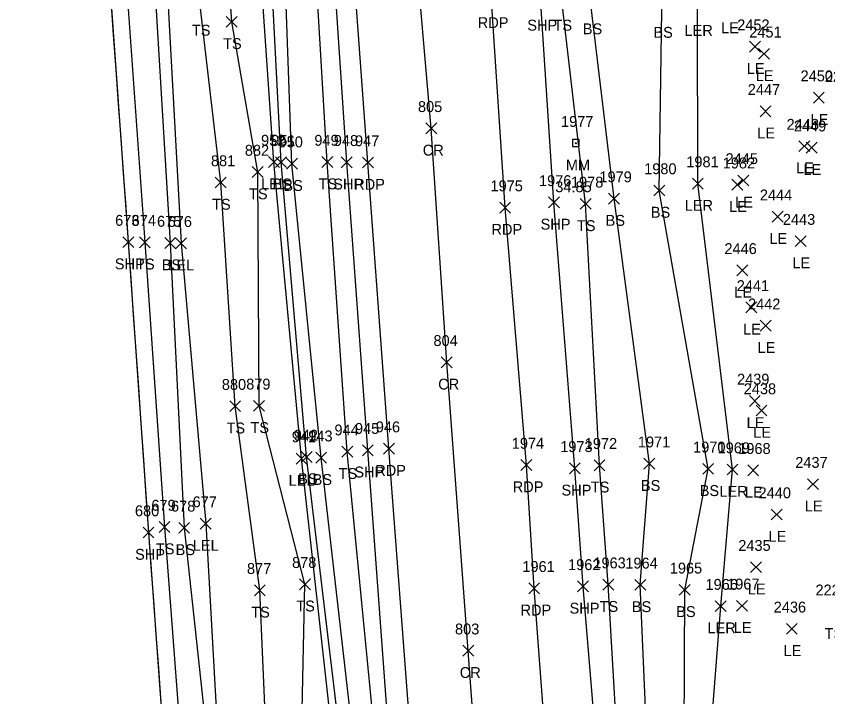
# Model space of a CAD drawing. Extents: x 1650221 to 1650634, y 244606 to 249996.
# Drawn here: x 1650345.8 to 1650494.9, y 245336 to 245461.1 of the extents above; entities that cross this region are included whole.
import ezdxf

# ---------------------------------------------------------------- set-up
doc = ezdxf.new("R2010")
doc.units = 0
for name, color, linetype in [('L_A', 7, 'Continuous'), ('L_I', 7, 'Continuous'), ('L_TIC', 7, 'Continuous'), ('LARO', 7, 'Continuous'), ('LELB', 7, 'Continuous'), ('LSOGP', 7, 'Continuous'), ('P_A', 7, 'Continuous'), ('P_I', 7, 'Continuous'), ('P_TIC', 7, 'Continuous'), ('PET', 7, 'Continuous'), ('PRC', 7, 'Continuous'), ('PSP', 7, 'Continuous'), ('S_A', 7, 'Continuous'), ('S_C', 7, 'Continuous'), ('S_I', 7, 'Continuous'), ('SRM', 7, 'Continuous')]:
    doc.layers.add(name, color=color, linetype=linetype)

msp = doc.modelspace()

# ---------------------------------------------------------------- linework, layer by layer
at = {"layer": 'L_TIC'}
for points in [[(1650384.39, 245459.04), (1650386.39, 245461.04)], [(1650386.39, 245459.04), (1650384.39, 245461.04)], [(1650480.56, 245454.48), (1650482.56, 245456.48)], [(1650482.56, 245454.48), (1650480.56, 245456.48)], [(1650482.21, 245453.16), (1650484.21, 245455.16)], [(1650484.21, 245453.16), (1650482.21, 245455.16)], [(1650492.3, 245445.11), (1650494.3, 245447.11)], [(1650494.3, 245445.11), (1650492.3, 245447.11)], [(1650482.5, 245442.61), (1650484.5, 245444.61)], [(1650484.5, 245442.61), (1650482.5, 245444.61)], [(1650489.64, 245436.2), (1650491.64, 245438.2)], [(1650491.64, 245436.2), (1650489.64, 245438.2)], [(1650490.98, 245435.9), (1650492.98, 245437.9)], [(1650492.98, 245435.9), (1650490.98, 245437.9)], [(1650392.14, 245433.28), (1650394.14, 245435.28)], [(1650394.14, 245433.28), (1650392.14, 245435.28)], [(1650393.45, 245433.24), (1650395.45, 245435.24)], [(1650395.45, 245433.24), (1650393.45, 245435.24)], [(1650395.45, 245432.97), (1650397.45, 245434.97)], [(1650397.45, 245432.97), (1650395.45, 245434.97)], [(1650401.95, 245433.27), (1650403.95, 245435.27)], [(1650403.95, 245433.27), (1650401.95, 245435.27)], [(1650389.16, 245431.43), (1650391.16, 245433.43)], [(1650391.16, 245431.43), (1650389.16, 245433.43)], [(1650478.42, 245429.89), (1650480.42, 245431.89)], [(1650480.42, 245429.89), (1650478.42, 245431.89)], [(1650382.37, 245429.51), (1650384.37, 245431.51)], [(1650384.37, 245429.51), (1650382.37, 245431.51)], [(1650470.06, 245429.31), (1650472.06, 245431.31)], [(1650472.06, 245429.31), (1650470.06, 245431.31)], [(1650477.33, 245429.1), (1650479.33, 245431.1)], [(1650479.33, 245429.1), (1650477.33, 245431.1)], [(1650462.98, 245428.04), (1650464.98, 245430.04)], [(1650464.98, 245428.04), (1650462.98, 245430.04)], [(1650449.43, 245425.58), (1650451.43, 245427.58)], [(1650451.43, 245425.58), (1650449.43, 245427.58)], [(1650454.67, 245426.55), (1650456.67, 245428.55)], [(1650456.67, 245426.55), (1650454.67, 245428.55)], [(1650484.72, 245423.22), (1650486.72, 245425.22)], [(1650486.72, 245423.22), (1650484.72, 245425.22)], [(1650368.41, 245418.53), (1650370.41, 245420.53)], [(1650370.41, 245418.53), (1650368.41, 245420.53)], [(1650373.07, 245418.38), (1650375.07, 245420.38)], [(1650375.07, 245418.38), (1650373.07, 245420.38)], [(1650375.08, 245418.34), (1650377.08, 245420.34)], [(1650377.08, 245418.34), (1650375.08, 245420.34)], [(1650488.95, 245418.73), (1650490.95, 245420.73)], [(1650490.95, 245418.73), (1650488.95, 245420.73)], [(1650478.26, 245413.36), (1650480.26, 245415.36)], [(1650480.26, 245413.36), (1650478.26, 245415.36)], [(1650479.9, 245406.55), (1650481.9, 245408.55)], [(1650481.9, 245406.55), (1650479.9, 245408.55)], [(1650482.55, 245403.18), (1650484.55, 245405.18)], [(1650484.55, 245403.18), (1650482.55, 245405.18)], [(1650385.02, 245388.39), (1650387.02, 245390.39)], [(1650387.02, 245388.39), (1650385.02, 245390.39)], [(1650389.42, 245388.46), (1650391.42, 245390.46)], [(1650391.42, 245388.46), (1650389.42, 245390.46)], [(1650480.54, 245389.36), (1650482.54, 245391.36)], [(1650482.54, 245389.36), (1650480.54, 245391.36)], [(1650481.76, 245387.6), (1650483.76, 245389.6)], [(1650483.76, 245387.6), (1650481.76, 245389.6)], [(1650398.15, 245379.06), (1650400.15, 245381.06)], [(1650400.15, 245379.06), (1650398.15, 245381.06)], [(1650405.63, 245380.03), (1650407.63, 245382.03)], [(1650407.63, 245380.03), (1650405.63, 245382.03)], [(1650397.22, 245378.76), (1650399.22, 245380.76)], [(1650399.22, 245378.76), (1650397.22, 245380.76)], [(1650400.82, 245378.92), (1650402.82, 245380.92)], [(1650402.82, 245378.92), (1650400.82, 245380.92)], [(1650461.16, 245377.82), (1650463.16, 245379.82)], [(1650463.16, 245377.82), (1650461.16, 245379.82)], [(1650451.98, 245377.54), (1650453.98, 245379.54)], [(1650453.98, 245377.54), (1650451.98, 245379.54)], [(1650471.97, 245376.88), (1650473.97, 245378.88)], [(1650473.97, 245376.88), (1650471.97, 245378.88)], [(1650476.44, 245376.75), (1650478.44, 245378.75)], [(1650478.44, 245376.75), (1650476.44, 245378.75)], [(1650480.23, 245376.61), (1650482.23, 245378.61)], [(1650482.23, 245376.61), (1650480.23, 245378.61)], [(1650491.23, 245374.06), (1650493.23, 245376.06)], [(1650493.23, 245374.06), (1650491.23, 245376.06)], [(1650484.57, 245368.48), (1650486.57, 245370.48)], [(1650486.57, 245368.48), (1650484.57, 245370.48)], [(1650372.04, 245366.18), (1650374.04, 245368.18)], [(1650374.04, 245366.18), (1650372.04, 245368.18)], [(1650375.64, 245366.03), (1650377.64, 245368.03)], [(1650377.64, 245366.03), (1650375.64, 245368.03)], [(1650379.61, 245366.82), (1650381.61, 245368.82)], [(1650381.61, 245366.82), (1650379.61, 245368.82)], [(1650480.76, 245358.8), (1650482.76, 245360.8)], [(1650482.76, 245358.8), (1650480.76, 245360.8)], [(1650397.84, 245355.67), (1650399.84, 245357.67)], [(1650399.84, 245355.67), (1650397.84, 245357.67)], [(1650453.6, 245355.59), (1650455.6, 245357.59)], [(1650455.6, 245355.59), (1650453.6, 245357.59)], [(1650459.48, 245355.55), (1650461.48, 245357.55)], [(1650461.48, 245355.55), (1650459.48, 245357.55)], [(1650389.56, 245354.55), (1650391.56, 245356.55)], [(1650391.56, 245354.55), (1650389.56, 245356.55)], [(1650467.65, 245354.64), (1650469.65, 245356.64)], [(1650469.65, 245354.64), (1650467.65, 245356.64)], [(1650474.26, 245351.64), (1650476.26, 245353.64)], [(1650476.26, 245351.64), (1650474.26, 245353.64)], [(1650478.19, 245351.7), (1650480.19, 245353.7)], [(1650480.19, 245351.7), (1650478.19, 245353.7)], [(1650487.33, 245347.47), (1650489.33, 245349.47)], [(1650489.33, 245347.47), (1650487.33, 245349.47)]]:
    msp.add_lwpolyline(points, dxfattribs=at)
at = {"layer": 'LARO'}
for points in [[(1650491, 245121.86), (1650493.61, 245139.73), (1650488.81, 245187.64), (1650492.44, 245198.75), (1650485.3, 245221.37), (1650479.96, 245259.68), (1650476.93, 245285.6), (1650472.44, 245315.86), (1650475.26, 245352.64), (1650477.44, 245377.75), (1650471.06, 245430.31), (1650471.03, 245462.47), (1650469.65, 245517.3), (1650470.03, 245548.03), (1650459.64, 245596.52), (1650458.35, 245631.93), (1650449.5, 245684.33)], [(1650421.38, 244936.36), (1650423.35, 244936.27), (1650425.89, 244936.22), (1650434.3, 244938.37), (1650430.48, 244972), (1650427.02, 245018.52), (1650423.68, 245067.08), (1650420.77, 245123.48), (1650416.16, 245170.75), (1650416.29, 245170.75), (1650411.97, 245219.01), (1650407.36, 245272.17), (1650403.92, 245328.57), (1650398.22, 245379.76), (1650393.14, 245434.28), (1650390.04, 245478.89), (1650387.05, 245523.12), (1650386.02, 245551.2)], [(1650370.23, 245505.43), (1650373.27, 245470.75), (1650376.08, 245419.34), (1650380.61, 245367.82), (1650383.54, 245316.3), (1650388.29, 245270.51), (1650390.54, 245221.61), (1650394.38, 245168.62), (1650397.75, 245118.3), (1650404.08, 245063.51), (1650406.12, 245018.23), (1650409.93, 244966.8), (1650411.89, 244938.28)]]:
    msp.add_lwpolyline(points, dxfattribs=at)
at = {"layer": 'LELB'}
for points in [[(1650349.13, 245703.09), (1650351.39, 245660.59), (1650355.99, 245608.05), (1650358.47, 245560.96), (1650362.91, 245508.7), (1650365.76, 245471.06), (1650369.41, 245419.53), (1650373.04, 245367.18), (1650376.89, 245316.29), (1650379.01, 245269.77), (1650383.48, 245220.96), (1650387.1, 245168.26), (1650390.97, 245118.17), (1650394.99, 245063.19), (1650398.03, 245017.1), (1650401.94, 244967.25), (1650403.81, 244936.86), (1650407.34, 244889.23), (1650410.84, 244834.73), (1650414.52, 244785.95), (1650419.34, 244732.83), (1650422.93, 244682.99), (1650426.36, 244632.18), (1650427.51, 244611.7)], [(1650355.71, 245703.22), (1650358.45, 245660.47), (1650361.92, 245609.02), (1650362.95, 245561.76), (1650366.97, 245508.68), (1650370.97, 245471.38), (1650374.07, 245419.38), (1650376.64, 245367.03), (1650382.18, 245316.08), (1650385.68, 245270.43), (1650388.77, 245221.07), (1650390.77, 245168.69), (1650394.69, 245118), (1650401.29, 245063.19), (1650403.89, 245017.69), (1650406.99, 244966.96), (1650408.31, 244937.61), (1650413.12, 244889.16), (1650416.09, 244835.73), (1650420.51, 244786.1), (1650423.8, 244733.3), (1650426.51, 244682.57), (1650434.12, 244632.73), (1650437.01, 244612.78)], [(1650458.26, 244631.23), (1650456.79, 244671.65), (1650452.78, 244720.4), (1650448.37, 244766.08), (1650444.9, 244801.26), (1650441.62, 244837.94), (1650439.87, 244879.23), (1650437.68, 244923.9), (1650433.87, 244972.21), (1650429.49, 245017.89), (1650426.15, 245066.7), (1650422.69, 245123.12), (1650419.86, 245170.84), (1650416.52, 245219.13), (1650411.95, 245271.56), (1650407.71, 245328.35), (1650401.82, 245379.92), (1650396.45, 245433.97), (1650394.84, 245478.56), (1650392.49, 245522.5), (1650389.35, 245551.29), (1650385.12, 245588.75), (1650380.77, 245632.36), (1650373.15, 245685.41)], [(1650462.3, 244631.92), (1650459.1, 244671.43), (1650455.6, 244720.68), (1650451.8, 244765.92), (1650449.21, 244801.88), (1650446.61, 244838.72), (1650443.38, 244880.99), (1650440.04, 244922.8), (1650437.91, 244972.67), (1650433.82, 245018.12), (1650431.01, 245067.65), (1650425.84, 245123.86), (1650424.05, 245171.63), (1650419.6, 245218.92), (1650416.04, 245272.16), (1650411.76, 245328.09), (1650406.63, 245381.03), (1650402.95, 245434.27), (1650400.25, 245479.81), (1650396.41, 245522.79), (1650395.43, 245551.92), (1650392.44, 245589.61), (1650388.27, 245633.5), (1650384.04, 245685.26)], [(1650489.71, 244991.22), (1650489.69, 245009.71), (1650486.09, 245047.64), (1650483.87, 245079.25), (1650480.92, 245116.18), (1650479.42, 245140.42), (1650476.29, 245187.3), (1650474, 245221.05), (1650469.02, 245258.31), (1650465.71, 245285.05), (1650462.26, 245315.54), (1650460.48, 245356.55), (1650462.16, 245378.82), (1650455.67, 245427.55), (1650451.48, 245462.76), (1650449.79, 245512.44), (1650449.11, 245548.12), (1650443.42, 245590.47), (1650442.32, 245632.05), (1650435.43, 245684.43)], [(1650471.05, 245115.28), (1650468.74, 245140.33), (1650464.89, 245185.98), (1650463.25, 245221.34), (1650461.37, 245257.85), (1650459.32, 245284.8), (1650456.97, 245315.55), (1650454.6, 245356.59), (1650452.98, 245378.54), (1650450.43, 245426.58), (1650446.12, 245463.42), (1650443.52, 245512.09), (1650441.71, 245548.12), (1650438.37, 245589.38), (1650434.29, 245631.65), (1650429.68, 245683.37)], [(1650493.15, 245007.74), (1650488.13, 245047.67), (1650486.59, 245079.09), (1650485.35, 245117.44), (1650483.97, 245140), (1650485.34, 245188.31), (1650482.43, 245221.37), (1650477.25, 245258), (1650473.1, 245285.62), (1650468.47, 245315.46), (1650468.65, 245355.64), (1650472.97, 245377.88), (1650463.98, 245429.04), (1650464.45, 245462.11), (1650460.79, 245514.67), (1650465.46, 245547.92), (1650447.43, 245596.3), (1650450.46, 245632.25)], [(1650417.42, 245170.71), (1650414.29, 245218.92), (1650409.59, 245271.3), (1650405.4, 245327.96), (1650399.15, 245380.06), (1650394.45, 245434.24), (1650392.17, 245479.25), (1650388.55, 245523.47), (1650387.04, 245550.93), (1650374.54, 245599.04)], [(1650411.56, 245100.31), (1650410.98, 245134.62), (1650407.62, 245167.58), (1650401.15, 245195.95), (1650400.96, 245232.6), (1650396.91, 245255.72), (1650396.39, 245280.59), (1650392.18, 245317.33), (1650390.56, 245355.55), (1650386.02, 245389.39), (1650383.37, 245430.51), (1650379.67, 245462.51), (1650379.96, 245467.43), (1650380, 245489.06), (1650377.56, 245510.96), (1650374.72, 245546.33), (1650373.24, 245560.96), (1650373.27, 245589.26)], [(1650417.99, 245100.65), (1650416.66, 245133.49), (1650414.16, 245167.69), (1650410.2, 245197), (1650406.67, 245233.63), (1650402.8, 245260.5), (1650403.69, 245281.19), (1650397.99, 245316.2), (1650398.84, 245356.67), (1650390.42, 245389.46), (1650390.16, 245432.43), (1650385.39, 245460.04), (1650384.98, 245466.18), (1650387.77, 245488.08), (1650384.3, 245517.36), (1650381.95, 245546.8), (1650375.57, 245561.13), (1650373.27, 245589.26)]]:
    msp.add_lwpolyline(points, dxfattribs=at)
at = {"layer": 'LSOGP'}
msp.add_lwpolyline([(1650363.17, 245464), (1650363.62, 245457.65), (1650364.08, 245451.3), (1650364.54, 245444.95), (1650365, 245438.6), (1650365.45, 245432.25), (1650365.91, 245425.9), (1650366.37, 245419.55), (1650366.83, 245412.88), (1650367.3, 245406.21), (1650367.76, 245399.53), (1650368.23, 245392.86), (1650368.7, 245386.19), (1650369.16, 245379.52), (1650369.63, 245372.84), (1650370.09, 245366.17), (1650370.55, 245359.92), (1650371, 245353.67), (1650371.46, 245347.41), (1650371.91, 245341.16), (1650372.37, 245334.91)], dxfattribs=at)
at = {"layer": 'P_TIC'}
for points in [[(1650421.06, 245439.46), (1650423.06, 245441.46)], [(1650423.06, 245439.46), (1650421.06, 245441.46)], [(1650405.52, 245433.23), (1650407.52, 245435.23)], [(1650407.52, 245433.23), (1650405.52, 245435.23)], [(1650409.42, 245433.18), (1650411.42, 245435.18)], [(1650411.42, 245433.18), (1650409.42, 245435.18)], [(1650443.62, 245425.85), (1650445.62, 245427.85)], [(1650445.62, 245425.85), (1650443.62, 245427.85)], [(1650434.64, 245424.9), (1650436.64, 245426.9)], [(1650436.64, 245424.9), (1650434.64, 245426.9)], [(1650365.37, 245418.55), (1650367.37, 245420.55)], [(1650367.37, 245418.55), (1650365.37, 245420.55)], [(1650423.91, 245396.45), (1650425.91, 245398.45)], [(1650425.91, 245396.45), (1650423.91, 245398.45)], [(1650413.28, 245380.59), (1650415.28, 245382.59)], [(1650415.28, 245380.59), (1650413.28, 245382.59)], [(1650409.4, 245380.3), (1650411.4, 245382.3)], [(1650411.4, 245380.3), (1650409.4, 245382.3)], [(1650438.55, 245377.58), (1650440.55, 245379.58)], [(1650440.55, 245377.58), (1650438.55, 245379.58)], [(1650447.46, 245376.97), (1650449.46, 245378.97)], [(1650449.46, 245376.97), (1650447.46, 245378.97)], [(1650369.09, 245365.17), (1650371.09, 245367.17)], [(1650371.09, 245365.17), (1650369.09, 245367.17)], [(1650448.96, 245355.27), (1650450.96, 245357.27)], [(1650450.96, 245355.27), (1650448.96, 245357.27)], [(1650439.98, 245354.92), (1650441.98, 245356.92)], [(1650441.98, 245354.92), (1650439.98, 245356.92)], [(1650427.87, 245343.44), (1650429.87, 245345.44)], [(1650429.87, 245343.44), (1650427.87, 245345.44)]]:
    msp.add_lwpolyline(points, dxfattribs=at)
at = {"layer": 'PET'}
for points in [[(1650468.61, 244633.66), (1650465.16, 244679.18), (1650461.18, 244730.39), (1650457.78, 244777.29), (1650455.76, 244806.01), (1650453.3, 244838.79), (1650450.33, 244880.04), (1650447.22, 244922.32), (1650443.48, 244972.73), (1650440.49, 245018.18), (1650436.73, 245069.12), (1650432.63, 245123.79), (1650429.44, 245172.68), (1650426.2, 245218.76), (1650422.12, 245272.82), (1650418.28, 245328.28), (1650414.28, 245381.59), (1650410.42, 245434.18), (1650407.03, 245480.26), (1650404.25, 245522.13), (1650401.81, 245552.98), (1650399.16, 245589.27), (1650395.97, 245634.45), (1650392.36, 245685.55)], [(1650458.15, 245114.32), (1650456.62, 245139.84), (1650453.42, 245185.54), (1650451.1, 245220.97), (1650448.32, 245256.66), (1650446.89, 245283.96), (1650444.13, 245314.19), (1650440.98, 245355.92), (1650439.55, 245378.58), (1650435.64, 245425.9), (1650433.13, 245463.89), (1650429.51, 245512.19), (1650427.14, 245547.69), (1650424.3, 245587.11), (1650421.18, 245630.65), (1650417.91, 245681.78)]]:
    msp.add_lwpolyline(points, dxfattribs=at)
at = {"layer": 'PRC'}
msp.add_lwpolyline([(1650447.57, 245085.81), (1650443.28, 245144.22), (1650439.84, 245189.25), (1650436.21, 245244.62), (1650432.57, 245294.06), (1650428.87, 245344.44), (1650424.91, 245397.45), (1650422.06, 245440.46), (1650418.2, 245485.2), (1650414.81, 245534.63), (1650412.73, 245565.5), (1650409.49, 245611.37), (1650407.05, 245649.82), (1650403.01, 245697.04)], dxfattribs=at)
at = {"layer": 'PSP'}
for points in [[(1650345.78, 245703.18), (1650348.63, 245659.65), (1650352.24, 245608.27), (1650356.14, 245560.76), (1650359.83, 245508.67), (1650362.71, 245470.35), (1650366.37, 245419.55), (1650370.09, 245366.17), (1650373.73, 245316.16), (1650376.75, 245269.64), (1650380.21, 245220.67), (1650384.07, 245168.16), (1650387.54, 245117.86), (1650391.85, 245063.26), (1650394.9, 245017.42), (1650398.56, 244967.17), (1650400.8, 244936.49), (1650404.42, 244889.02), (1650408.47, 244833.97), (1650411.77, 244786.13), (1650415.79, 244732.16), (1650419.27, 244682.87), (1650423.02, 244632.43), (1650424.78, 244611.26)], [(1650464.84, 244632.07), (1650461.81, 244671.31), (1650457.94, 244720.75), (1650454.77, 244765.54), (1650451.99, 244802.46), (1650449.34, 244838.71), (1650446.5, 244879.72), (1650443.46, 244922.98), (1650439.98, 244973.19), (1650436.37, 245018.02), (1650433.26, 245068.28), (1650429.09, 245123.84), (1650425.59, 245171.99), (1650422.33, 245218.99), (1650418.38, 245272.19), (1650414.3, 245328), (1650410.4, 245381.3), (1650406.52, 245434.23), (1650403.48, 245480), (1650400.24, 245522.79), (1650398.25, 245552.46), (1650395.41, 245589.43), (1650392.23, 245633.8), (1650388.44, 245685.1)], [(1650467.35, 245115.19), (1650465.66, 245140.38), (1650462.4, 245185.76), (1650459.93, 245221.23), (1650457.1, 245257.2), (1650455.22, 245284.62), (1650453.41, 245314.94), (1650449.96, 245356.27), (1650448.46, 245377.97), (1650444.62, 245426.85), (1650442.19, 245463.43), (1650438.55, 245512.23), (1650436.23, 245548.05), (1650433.37, 245588.35), (1650430.25, 245631.19), (1650426.21, 245683.01)]]:
    msp.add_lwpolyline(points, dxfattribs=at)
at = {"layer": 'SRM'}
for p, q in [((1650449.26, 245438.39), (1650448.01, 245438.39)), ((1650448.01, 245438.39), (1650448.01, 245437.14)), ((1650449.26, 245438.39), (1650448.01, 245438.39)), ((1650448.01, 245438.39), (1650448.01, 245437.14)), ((1650449.26, 245437.14), (1650449.26, 245438.39)), ((1650449.26, 245437.14), (1650449.26, 245438.39)), ((1650448.01, 245437.14), (1650449.26, 245437.14)), ((1650448.01, 245437.14), (1650449.26, 245437.14))]:
    msp.add_line(p, q, dxfattribs=at)
msp.add_circle((1650448.61, 245437.73), 0.0833, dxfattribs=at)

# ---------------------------------------------------------------- texts
at = {"layer": 'L_A'}
for s, p in [('TS', (1650444.53, 245458.42)), ('TS', (1650378.07, 245457.51)), ('BS', (1650449.92, 245457.76)), ('BS', (1650462.9, 245457.11)), ('LER', (1650468.61, 245457.47)), ('LE', (1650475.35, 245457.96)), ('TS', (1650383.8, 245455.04)), ('LE', (1650480.05, 245450.48)), ('LE', (1650481.7, 245449.16)), ('LE', (1650491.79, 245441.11)), ('LE', (1650481.98, 245438.61)), ('LE', (1650489.12, 245432.2)), ('LE', (1650490.47, 245431.9)), ('LEL', (1650390.78, 245429.28)), ('BS', (1650392.89, 245429.24)), ('BS', (1650394.89, 245428.97)), ('TS', (1650401.36, 245429.27)), ('TS', (1650388.57, 245427.43)), ('TS', (1650381.78, 245425.51)), ('LER', (1650468.65, 245425.31)), ('LE', (1650477.91, 245425.89)), ('BS', (1650462.42, 245424.04)), ('LE', (1650476.82, 245425.1)), ('BS', (1650454.11, 245422.55)), ('TS', (1650448.84, 245421.58)), ('LE', (1650484.2, 245419.22)), ('TS', (1650367.81, 245414.53)), ('BS', (1650372.51, 245414.38)), ('LEL', (1650373.72, 245414.34)), ('LE', (1650488.44, 245414.73)), ('LE', (1650477.75, 245409.36)), ('LE', (1650479.39, 245402.55)), ('LE', (1650482.04, 245399.18)), ('LE', (1650480.03, 245385.36)), ('TS', (1650384.43, 245384.39)), ('TS', (1650388.83, 245384.46)), ('LE', (1650481.25, 245383.6)), ('LEL', (1650395.85, 245374.76)), ('BS', (1650397.6, 245375.06)), ('BS', (1650400.26, 245374.92)), ('TS', (1650405.04, 245376.03)), ('TS', (1650451.39, 245373.54)), ('BS', (1650460.6, 245373.82)), ('BS', (1650471.41, 245372.88)), ('LER', (1650475.02, 245372.75)), ('LE', (1650479.72, 245372.61)), ('LE', (1650490.72, 245370.06)), ('LE', (1650484.06, 245364.48)), ('LEL', (1650378.24, 245362.82)), ('TS', (1650371.45, 245362.18)), ('BS', (1650375.08, 245362.03)), ('LE', (1650480.24, 245354.8)), ('TS', (1650397.25, 245351.67)), ('TS', (1650453.01, 245351.59)), ('BS', (1650458.93, 245351.55)), ('TS', (1650388.97, 245350.55)), ('BS', (1650467.09, 245350.64)), ('LER', (1650472.84, 245347.64)), ('LE', (1650477.67, 245347.7)), ('TS', (1650494.36, 245346.61)), ('LE', (1650486.82, 245343.47))]:
    msp.add_text(s, height=2, dxfattribs=at).set_placement(p)
at = {"layer": 'L_I'}
for s, p in [('2452', (1650478.3, 245458.48)), ('2451', (1650480.52, 245457.16)), ('2450', (1650489.95, 245449.11)), ('2229', (1650494.41, 245448.99)), ('2447', (1650480.24, 245446.61)), ('2448', (1650487.38, 245440.2)), ('2449', (1650488.71, 245439.9)), ('952', (1650390.78, 245437.28)), ('951', (1650392.65, 245437.24)), ('949', (1650400.58, 245437.27)), ('950', (1650394, 245436.97)), ('882', (1650387.8, 245435.43)), ('881', (1650381.57, 245433.51)), ('1981', (1650468.94, 245433.31)), ('1982', (1650475.64, 245433.1)), ('2445', (1650476.16, 245433.89)), ('1980', (1650461.2, 245432.04)), ('1979', (1650452.97, 245430.55)), ('1978', (1650447.74, 245429.58)), ('2444', (1650482.46, 245427.22)), ('674', (1650367, 245422.53)), ('675', (1650371.66, 245422.38)), ('676', (1650373.62, 245422.34)), ('2443', (1650486.69, 245422.73)), ('2446', (1650475.95, 245417.36)), ('2441', (1650478.21, 245410.55)), ('2442', (1650480.29, 245407.18)), ('879', (1650388.05, 245392.46)), ('2439', (1650478.27, 245393.36)), ('880', (1650383.57, 245392.39)), ('2438', (1650479.5, 245391.6)), ('944', (1650404.27, 245384.03)), ('941', (1650396.42, 245382.76)), ('942', (1650396.79, 245383.06)), ('943', (1650399.46, 245382.92)), ('1972', (1650450.28, 245381.54)), ('1971', (1650460.04, 245381.82)), ('1970', (1650470.19, 245380.88)), ('1969', (1650474.69, 245380.75)), ('1968', (1650478.49, 245380.61)), ('2437', (1650488.97, 245378.06)), ('2440', (1650482.23, 245372.48)), ('679', (1650370.62, 245370.18)), ('677', (1650378.2, 245370.82)), ('678', (1650374.23, 245370.03)), ('2435', (1650478.5, 245362.8)), ('878', (1650396.48, 245359.67)), ('877', (1650388.19, 245358.55)), ('1963', (1650451.86, 245359.59)), ('1964', (1650457.74, 245359.55)), ('1965', (1650465.91, 245358.64)), ('1966', (1650472.47, 245355.64)), ('1967', (1650476.45, 245355.7)), ('2225', (1650492.69, 245354.61)), ('2436', (1650485.01, 245351.47))]:
    msp.add_text(s, height=2, dxfattribs=at).set_placement(p)
at = {"layer": 'P_A'}
for s, p in [('RDP', (1650430.61, 245458.89)), ('SHP', (1650439.72, 245458.43)), ('CR', (1650420.5, 245435.46)), ('SHP', (1650404.05, 245429.23)), ('RDP', (1650407.9, 245429.18)), ('RDP', (1650433.13, 245420.9)), ('SHP', (1650442.16, 245421.85)), ('SHP', (1650363.9, 245414.55)), ('CR', (1650423.34, 245392.45)), ('SHP', (1650407.94, 245376.3)), ('RDP', (1650411.77, 245376.59)), ('RDP', (1650437.04, 245373.58)), ('SHP', (1650446, 245372.97)), ('SHP', (1650367.63, 245361.17)), ('RDP', (1650438.47, 245350.92)), ('SHP', (1650447.49, 245351.27)), ('CR', (1650427.3, 245339.44))]:
    msp.add_text(s, height=2, dxfattribs=at).set_placement(p)
at = {"layer": 'P_I'}
for s, p in [('805', (1650419.62, 245443.46)), ('948', (1650404.15, 245437.23)), ('947', (1650408.05, 245437.18)), ('1976', (1650441.87, 245429.85)), ('1975', (1650432.95, 245428.9)), ('673', (1650363.96, 245422.55)), ('804', (1650422.47, 245400.45)), ('945', (1650408.04, 245384.3)), ('946', (1650411.87, 245384.59)), ('1974', (1650436.86, 245381.58)), ('1973', (1650445.77, 245380.97)), ('680', (1650367.6, 245369.17)), ('1961', (1650438.81, 245358.92)), ('1962', (1650447.22, 245359.27)), ('803', (1650426.43, 245347.44))]:
    msp.add_text(s, height=2, dxfattribs=at).set_placement(p)
at = {"layer": 'S_A'}
msp.add_text('MM', height=2, dxfattribs=at).set_placement((1650446.8, 245432.73))
at = {"layer": 'S_C'}
msp.add_text('34.85', height=2, dxfattribs=at).set_placement((1650444.86, 245428.73))
at = {"layer": 'S_I'}
msp.add_text('1977', height=2, dxfattribs=at).set_placement((1650445.92, 245440.73))

doc.saveas('drawing.dxf')
